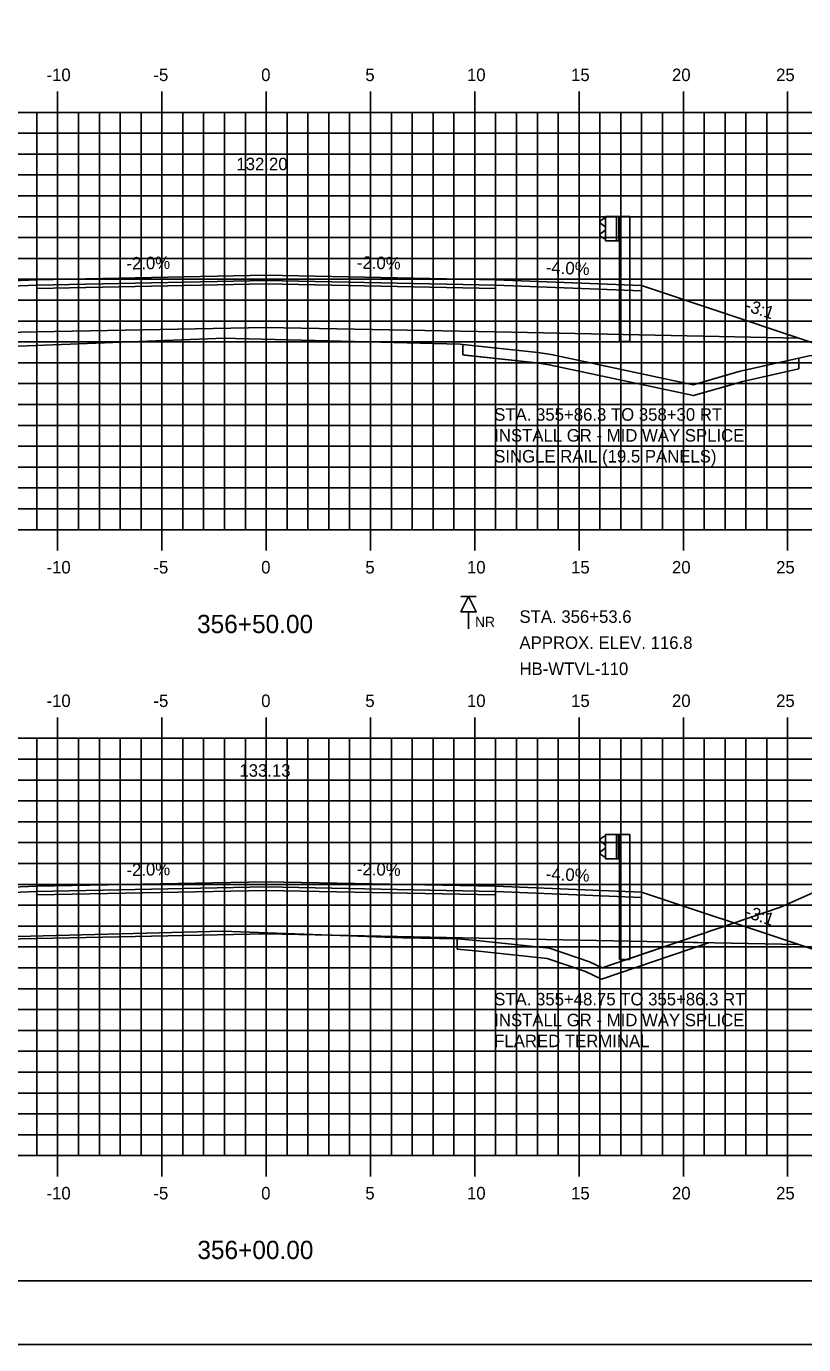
# Model space of a CAD drawing. Extents: x 1145638 to 1145808, y 608981 to 609091.
# Drawn here: x 1145709.1 to 1145746.4, y 608981.3 to 609044.5 of the extents above; entities that cross this region are included whole.
import ezdxf

# ---------------------------------------------------------------- set-up
doc = ezdxf.new("R2010")
doc.units = 0
for name, color, linetype in [('ANNOTATION', 7, 'Continuous'), ('BORDER', 7, 'Continuous'), ('D_Guardrail_Beam_Rt', 7, 'Continuous'), ('D_Guardrail_ConcBarrier', 7, 'Continuous'), ('D_Roadway_Centerline', 7, 'Continuous'), ('D_Roadway_Centerline_Text', 7, 'Continuous'), ('D_Roadway_Edge_Shoulder', 7, 'Continuous'), ('D_Roadway_Edge_TW', 7, 'Continuous'), ('D_Roadway_Pavement', 7, 'Continuous'), ('D_Roadway_SlopeLines', 7, 'Continuous'), ('D_Roadway_SubGrade', 7, 'Continuous'), ('H_V ANNOTATION', 7, 'Continuous'), ('MAJOR', 7, 'Continuous'), ('MINOR', 7, 'Continuous'), ('PLOT BOUNDARY', 7, 'Continuous'), ('ROCKS', 7, 'Continuous'), ('S_Roadway_Centerline', 7, 'Continuous'), ('SHADING', 7, 'Continuous')]:
    doc.layers.add(name, color=color, linetype=linetype)

msp = doc.modelspace()

# ---------------------------------------------------------------- linework, layer by layer
for points in [[(1145681.258, 609032.341), (1145682.508, 609032.231), (1145683.758, 609031.973), (1145685.008, 609031.568), (1145686.258, 609031.017), (1145691.284, 609028.504), (1145694.284, 609029.504), (1145701.76, 609031.996), (1145701.761, 609031.996), (1145709.645, 609032.311), (1145720.645, 609032.531), (1145731.645, 609032.311), (1145738.645, 609032.031), (1145746.177, 609029.52), (1145749.177, 609028.52), (1145749.6, 609028.71), (1145750.023, 609028.855), (1145750.446, 609028.957), (1145750.869, 609029.014)], [(1145683.903, 609003.924), (1145685.153, 609003.777), (1145686.403, 609003.494), (1145687.653, 609003.074), (1145688.903, 609002.517), (1145694.92, 608999.509), (1145697.92, 609000.509), (1145705.644, 609003.083), (1145705.645, 609003.083), (1145709.645, 609003.243), (1145720.645, 609003.463), (1145731.645, 609003.243), (1145738.645, 609002.963), (1145746.177, 609000.453), (1145749.177, 608999.453), (1145755.422, 609002.575), (1145756.672, 609003.138), (1145757.922, 609003.576), (1145759.172, 609003.888), (1145760.422, 609004.076)]]:
    msp.add_lwpolyline(points)
at = {"layer": 'BORDER'}
msp.add_lwpolyline([(1145645.645, 608984.335), (1145805.645, 608984.335), (1145805.645, 609089.335), (1145645.645, 609089.335)], close=True, dxfattribs=at)
at = {"layer": 'D_Guardrail_Beam_Rt'}
for p, q in [((1145736.828, 609035.247), (1145736.685, 609035.147)), ((1145736.685, 609035.004), (1145736.88, 609034.868)), ((1145736.918, 609035.268), (1145736.844, 609035.254)), ((1145736.914, 609034.803), (1145736.914, 609034.733)), ((1145736.88, 609034.669), (1145736.685, 609034.533)), ((1145736.685, 609034.389), (1145736.828, 609034.289)), ((1145736.844, 609034.283), (1145736.918, 609034.268)), ((1145736.916, 609005.647), (1145736.841, 609005.633)), ((1145736.826, 609005.626), (1145736.682, 609005.526)), ((1145736.682, 609005.383), (1145736.878, 609005.247)), ((1145736.878, 609005.048), (1145736.682, 609004.912)), ((1145736.911, 609005.182), (1145736.911, 609005.112)), ((1145736.682, 609004.768), (1145736.826, 609004.668)), ((1145736.841, 609004.662), (1145736.916, 609004.647))]:
    msp.add_line(p, q, dxfattribs=at)
for centre, major_axis, start_param, end_param in [((1145736.735, 609035.075), (-0.0877, 0), 5.323254, 7.243116), ((1145736.852, 609035.213), (-0.0417, 0), 4.907132, 5.323254), ((1145736.835, 609034.803), (0.0789, 0), 0, 0.959931), ((1145736.835, 609034.733), (0.0789, 0), 5.323254, 6.283185), ((1145736.735, 609034.461), (-0.0877, 0), 5.323254, 7.243116), ((1145736.852, 609034.323), (-0.0417, 0), 0.959931, 1.376053), ((1145736.85, 609005.592), (-0.0417, 0), 4.907132, 5.323254), ((1145736.732, 609005.454), (-0.0877, 0), 5.323254, 7.243116), ((1145736.832, 609005.182), (0.0789, 0), 0, 0.959931), ((1145736.832, 609005.112), (0.0789, 0), 5.323254, 6.283185), ((1145736.732, 609004.84), (-0.0877, 0), 5.323254, 7.243116), ((1145736.85, 609004.702), (-0.0417, 0), 0.959931, 1.376053)]:
    msp.add_ellipse(centre, major_axis=major_axis, ratio=0.995501, start_param=start_param, end_param=end_param, dxfattribs=at)
at = {"layer": 'D_Guardrail_ConcBarrier'}
for p, q in [((1145736.918, 609035.352), (1145737.606, 609035.352)), ((1145736.918, 609034.185), (1145736.918, 609035.352)), ((1145737.439, 609035.352), (1145737.439, 609034.185)), ((1145737.543, 609035.352), (1145737.543, 609034.185)), ((1145737.606, 609035.352), (1145738.077, 609035.352)), ((1145737.606, 609035.352), (1145737.606, 609034.185)), ((1145738.077, 609035.352), (1145738.077, 609029.352)), ((1145737.606, 609034.185), (1145736.918, 609034.185)), ((1145737.585, 609029.352), (1145737.585, 609034.185)), ((1145737.585, 609029.352), (1145738.077, 609029.352)), ((1145736.916, 609005.731), (1145737.603, 609005.731)), ((1145736.916, 609004.564), (1145736.916, 609005.731)), ((1145737.436, 609005.731), (1145737.436, 609004.564)), ((1145737.541, 609005.731), (1145737.541, 609004.564)), ((1145737.603, 609005.731), (1145738.074, 609005.731)), ((1145737.603, 609005.731), (1145737.603, 609004.564)), ((1145738.074, 609005.731), (1145738.074, 608999.731)), ((1145737.603, 609004.564), (1145736.916, 609004.564)), ((1145737.582, 608999.731), (1145737.582, 609004.564)), ((1145737.582, 608999.731), (1145738.074, 608999.731))]:
    msp.add_line(p, q, dxfattribs=at)
at = {"layer": 'D_Roadway_Edge_Shoulder'}
for points in [[(1145709.645, 609032.311), (1145701.761, 609031.996), (1145701.761, 609031.746), (1145709.645, 609032.061)], [(1145731.645, 609032.311), (1145738.645, 609032.031), (1145738.645, 609031.781), (1145731.645, 609032.061)], [(1145709.645, 609003.243), (1145705.645, 609003.083), (1145705.645, 609002.833), (1145709.645, 609002.993)], [(1145731.645, 609003.243), (1145738.645, 609002.963), (1145738.645, 609002.713), (1145731.645, 609002.993)]]:
    msp.add_lwpolyline(points, close=True, dxfattribs=at)
at = {"layer": 'D_Roadway_Edge_TW'}
for points in [[(1145709.645, 609032.061), (1145709.645, 609032.311), (1145720.645, 609032.531), (1145731.645, 609032.311), (1145731.645, 609032.061), (1145720.645, 609032.281)], [(1145709.645, 609002.993), (1145709.645, 609003.243), (1145720.645, 609003.463), (1145731.645, 609003.243), (1145731.645, 609002.993), (1145720.645, 609003.213)]]:
    msp.add_lwpolyline(points, close=True, dxfattribs=at)
at = {"layer": 'D_Roadway_Pavement'}
for points in [[(1145709.645, 609031.894), (1145709.645, 609032.061), (1145720.645, 609032.281), (1145731.645, 609032.061), (1145731.645, 609031.894), (1145720.645, 609032.114)], [(1145709.645, 609002.827), (1145709.645, 609002.993), (1145720.645, 609003.213), (1145731.645, 609002.993), (1145731.645, 609002.827), (1145720.645, 609003.047)]]:
    msp.add_lwpolyline(points, close=True, dxfattribs=at)
at = {"layer": 'D_Roadway_SlopeLines'}
for points in [[(1145746.177, 609029.52), (1145749.177, 609028.52)], [(1145746.177, 609000.453), (1145749.177, 608999.453)]]:
    msp.add_lwpolyline(points, dxfattribs=at)
at = {"layer": 'D_Roadway_SubGrade'}
for p, q in [((1145730.075, 609029.216), (1145730.075, 609028.716)), ((1145746.177, 609028.553), (1145746.177, 609028.042)), ((1145729.795, 609000.725), (1145729.795, 609000.223))]:
    msp.add_line(p, q, dxfattribs=at)
for points in [[(1145709.645, 609031.894), (1145709.645, 609032.061), (1145701.761, 609031.746), (1145701.761, 609031.996), (1145701.76, 609031.996), (1145694.284, 609029.504), (1145709.645, 609029.811)], [(1145709.645, 609029.811), (1145709.645, 609031.894), (1145720.645, 609032.114), (1145731.645, 609031.894), (1145731.645, 609029.811), (1145720.645, 609030.031)], [(1145731.645, 609031.894), (1145731.645, 609032.061), (1145738.645, 609031.781), (1145738.645, 609032.031), (1145738.645, 609032.031), (1145746.177, 609029.52), (1145731.645, 609029.811)], [(1145709.645, 609002.827), (1145709.645, 609002.993), (1145705.645, 609002.833), (1145705.645, 609003.083), (1145705.644, 609003.083), (1145697.92, 609000.509), (1145709.645, 609000.743)], [(1145709.645, 609000.743), (1145709.645, 609002.827), (1145720.645, 609003.047), (1145731.645, 609002.827), (1145731.645, 609000.743), (1145720.645, 609000.963)], [(1145731.645, 609002.827), (1145731.645, 609002.993), (1145738.645, 609002.713), (1145738.645, 609002.963), (1145738.645, 609002.963), (1145746.177, 609000.453), (1145731.645, 609000.743)]]:
    msp.add_lwpolyline(points, close=True, dxfattribs=at)
for points in [[(1145730.075, 609028.714), (1145730.157, 609028.705), (1145733.608, 609028.334), (1145734.215, 609028.241), (1145741.13, 609026.762), (1145743.498, 609027.442), (1145746.177, 609028.042)], [(1145729.795, 609000.223), (1145730.678, 609000.144), (1145734.119, 608999.779), (1145735.958, 608999.156), (1145736.723, 608998.795), (1145741.853, 609000.539)]]:
    msp.add_lwpolyline(points, dxfattribs=at)
at = {"layer": 'MAJOR'}
for p, q in [((1145710.645, 609041.337), (1145710.645, 609040.335)), ((1145715.645, 609041.337), (1145715.645, 609040.335)), ((1145720.645, 609041.337), (1145720.645, 609040.335)), ((1145725.645, 609041.337), (1145725.645, 609040.335)), ((1145730.645, 609041.337), (1145730.645, 609040.335)), ((1145735.645, 609041.337), (1145735.645, 609040.335)), ((1145740.645, 609041.337), (1145740.645, 609040.335)), ((1145745.645, 609041.337), (1145745.645, 609040.335)), ((1145650.645, 609040.335), (1145790.645, 609040.335)), ((1145650.645, 609040.335), (1145790.645, 609040.335)), ((1145710.645, 609020.335), (1145710.645, 609040.335)), ((1145715.645, 609020.335), (1145715.645, 609040.335)), ((1145720.645, 609020.335), (1145720.645, 609040.335)), ((1145725.645, 609020.335), (1145725.645, 609040.335)), ((1145730.645, 609020.335), (1145730.645, 609040.335)), ((1145735.645, 609020.335), (1145735.645, 609040.335)), ((1145740.645, 609020.335), (1145740.645, 609040.335)), ((1145745.645, 609020.335), (1145745.645, 609040.335)), ((1145650.645, 609035.335), (1145790.645, 609035.335)), ((1145650.645, 609030.335), (1145790.645, 609030.335)), ((1145650.645, 609025.335), (1145790.645, 609025.335)), ((1145650.645, 609020.335), (1145790.645, 609020.335)), ((1145650.645, 609020.335), (1145790.645, 609020.335)), ((1145710.645, 609019.333), (1145710.645, 609020.335)), ((1145715.645, 609019.333), (1145715.645, 609020.335)), ((1145720.645, 609019.333), (1145720.645, 609020.335)), ((1145725.645, 609019.333), (1145725.645, 609020.335)), ((1145730.645, 609019.333), (1145730.645, 609020.335)), ((1145735.645, 609019.333), (1145735.645, 609020.335)), ((1145740.645, 609019.333), (1145740.645, 609020.335)), ((1145745.645, 609019.333), (1145745.645, 609020.335)), ((1145710.645, 609011.337), (1145710.645, 609010.335)), ((1145715.645, 609011.337), (1145715.645, 609010.335)), ((1145720.645, 609011.337), (1145720.645, 609010.335)), ((1145725.645, 609011.337), (1145725.645, 609010.335)), ((1145730.645, 609011.337), (1145730.645, 609010.335)), ((1145735.645, 609011.337), (1145735.645, 609010.335)), ((1145740.645, 609011.337), (1145740.645, 609010.335)), ((1145745.645, 609011.337), (1145745.645, 609010.335)), ((1145650.645, 609010.335), (1145790.645, 609010.335)), ((1145650.645, 609010.335), (1145790.645, 609010.335)), ((1145710.645, 608990.335), (1145710.645, 609010.335)), ((1145715.645, 608990.335), (1145715.645, 609010.335)), ((1145720.645, 608990.335), (1145720.645, 609010.335)), ((1145725.645, 608990.335), (1145725.645, 609010.335)), ((1145730.645, 608990.335), (1145730.645, 609010.335)), ((1145735.645, 608990.335), (1145735.645, 609010.335)), ((1145740.645, 608990.335), (1145740.645, 609010.335)), ((1145745.645, 608990.335), (1145745.645, 609010.335)), ((1145650.645, 609005.335), (1145790.645, 609005.335)), ((1145650.645, 609000.335), (1145790.645, 609000.335)), ((1145650.645, 608995.335), (1145790.645, 608995.335)), ((1145650.645, 608990.335), (1145790.645, 608990.335)), ((1145650.645, 608990.335), (1145790.645, 608990.335)), ((1145710.645, 608989.333), (1145710.645, 608990.335)), ((1145715.645, 608989.333), (1145715.645, 608990.335)), ((1145720.645, 608989.333), (1145720.645, 608990.335)), ((1145725.645, 608989.333), (1145725.645, 608990.335)), ((1145730.645, 608989.333), (1145730.645, 608990.335)), ((1145735.645, 608989.333), (1145735.645, 608990.335)), ((1145740.645, 608989.333), (1145740.645, 608990.335)), ((1145745.645, 608989.333), (1145745.645, 608990.335))]:
    msp.add_line(p, q, dxfattribs=at)
at = {"layer": 'MINOR'}
for p, q in [((1145709.645, 609020.335), (1145709.645, 609040.335)), ((1145711.645, 609020.335), (1145711.645, 609040.335)), ((1145712.645, 609020.335), (1145712.645, 609040.335)), ((1145713.645, 609020.335), (1145713.645, 609040.335)), ((1145714.645, 609020.335), (1145714.645, 609040.335)), ((1145716.645, 609020.335), (1145716.645, 609040.335)), ((1145717.645, 609020.335), (1145717.645, 609040.335)), ((1145718.645, 609020.335), (1145718.645, 609040.335)), ((1145719.645, 609020.335), (1145719.645, 609040.335)), ((1145721.645, 609020.335), (1145721.645, 609040.335)), ((1145722.645, 609020.335), (1145722.645, 609040.335)), ((1145723.645, 609020.335), (1145723.645, 609040.335)), ((1145724.645, 609020.335), (1145724.645, 609040.335)), ((1145726.645, 609020.335), (1145726.645, 609040.335)), ((1145727.645, 609020.335), (1145727.645, 609040.335)), ((1145728.645, 609020.335), (1145728.645, 609040.335)), ((1145729.645, 609020.335), (1145729.645, 609040.335)), ((1145731.645, 609020.335), (1145731.645, 609040.335)), ((1145732.645, 609020.335), (1145732.645, 609040.335)), ((1145733.645, 609020.335), (1145733.645, 609040.335)), ((1145734.645, 609020.335), (1145734.645, 609040.335)), ((1145736.645, 609020.335), (1145736.645, 609040.335)), ((1145737.645, 609020.335), (1145737.645, 609040.335)), ((1145738.645, 609020.335), (1145738.645, 609040.335)), ((1145739.645, 609020.335), (1145739.645, 609040.335)), ((1145741.645, 609020.335), (1145741.645, 609040.335)), ((1145742.645, 609020.335), (1145742.645, 609040.335)), ((1145743.645, 609020.335), (1145743.645, 609040.335)), ((1145744.645, 609020.335), (1145744.645, 609040.335)), ((1145650.645, 609039.335), (1145790.645, 609039.335)), ((1145650.645, 609038.335), (1145790.645, 609038.335)), ((1145650.645, 609037.335), (1145790.645, 609037.335)), ((1145650.645, 609036.335), (1145790.645, 609036.335)), ((1145650.645, 609034.335), (1145790.645, 609034.335)), ((1145650.645, 609033.335), (1145790.645, 609033.335)), ((1145650.645, 609032.335), (1145790.645, 609032.335)), ((1145650.645, 609031.335), (1145790.645, 609031.335)), ((1145650.645, 609029.335), (1145790.645, 609029.335)), ((1145650.645, 609028.335), (1145790.645, 609028.335)), ((1145650.645, 609027.335), (1145790.645, 609027.335)), ((1145650.645, 609026.335), (1145790.645, 609026.335)), ((1145650.645, 609024.335), (1145790.645, 609024.335)), ((1145650.645, 609023.335), (1145790.645, 609023.335)), ((1145650.645, 609022.335), (1145790.645, 609022.335)), ((1145650.645, 609021.335), (1145790.645, 609021.335)), ((1145709.645, 608990.335), (1145709.645, 609010.335)), ((1145711.645, 608990.335), (1145711.645, 609010.335)), ((1145712.645, 608990.335), (1145712.645, 609010.335)), ((1145713.645, 608990.335), (1145713.645, 609010.335)), ((1145714.645, 608990.335), (1145714.645, 609010.335)), ((1145716.645, 608990.335), (1145716.645, 609010.335)), ((1145717.645, 608990.335), (1145717.645, 609010.335)), ((1145718.645, 608990.335), (1145718.645, 609010.335)), ((1145719.645, 608990.335), (1145719.645, 609010.335)), ((1145721.645, 608990.335), (1145721.645, 609010.335)), ((1145722.645, 608990.335), (1145722.645, 609010.335)), ((1145723.645, 608990.335), (1145723.645, 609010.335)), ((1145724.645, 608990.335), (1145724.645, 609010.335)), ((1145726.645, 608990.335), (1145726.645, 609010.335)), ((1145727.645, 608990.335), (1145727.645, 609010.335)), ((1145728.645, 608990.335), (1145728.645, 609010.335)), ((1145729.645, 608990.335), (1145729.645, 609010.335)), ((1145731.645, 608990.335), (1145731.645, 609010.335)), ((1145732.645, 608990.335), (1145732.645, 609010.335)), ((1145733.645, 608990.335), (1145733.645, 609010.335)), ((1145734.645, 608990.335), (1145734.645, 609010.335)), ((1145736.645, 608990.335), (1145736.645, 609010.335)), ((1145737.645, 608990.335), (1145737.645, 609010.335)), ((1145738.645, 608990.335), (1145738.645, 609010.335)), ((1145739.645, 608990.335), (1145739.645, 609010.335)), ((1145741.645, 608990.335), (1145741.645, 609010.335)), ((1145742.645, 608990.335), (1145742.645, 609010.335)), ((1145743.645, 608990.335), (1145743.645, 609010.335)), ((1145744.645, 608990.335), (1145744.645, 609010.335)), ((1145650.645, 609009.335), (1145790.645, 609009.335)), ((1145650.645, 609008.335), (1145790.645, 609008.335)), ((1145650.645, 609007.335), (1145790.645, 609007.335)), ((1145650.645, 609006.335), (1145790.645, 609006.335)), ((1145650.645, 609004.335), (1145790.645, 609004.335)), ((1145650.645, 609003.335), (1145790.645, 609003.335)), ((1145650.645, 609002.335), (1145790.645, 609002.335)), ((1145650.645, 609001.335), (1145790.645, 609001.335)), ((1145650.645, 608999.335), (1145790.645, 608999.335)), ((1145650.645, 608998.335), (1145790.645, 608998.335)), ((1145650.645, 608997.335), (1145790.645, 608997.335)), ((1145650.645, 608996.335), (1145790.645, 608996.335)), ((1145650.645, 608994.335), (1145790.645, 608994.335)), ((1145650.645, 608993.335), (1145790.645, 608993.335)), ((1145650.645, 608992.335), (1145790.645, 608992.335)), ((1145650.645, 608991.335), (1145790.645, 608991.335))]:
    msp.add_line(p, q, dxfattribs=at)
at = {"layer": 'PLOT BOUNDARY'}
msp.add_lwpolyline([(1145637.552, 608981.276), (1145807.552, 608981.276), (1145807.552, 609091.276), (1145637.552, 609091.276)], close=True, dxfattribs=at)
at = {"layer": 'ROCKS'}
for p, q in [((1145730.714, 609017.135), (1145729.976, 609017.135)), ((1145730.345, 609016.397), (1145730.345, 609015.582))]:
    msp.add_line(p, q, dxfattribs=at)
msp.add_lwpolyline([(1145730.345, 609017.135), (1145730.714, 609016.397), (1145729.976, 609016.397)], close=True, dxfattribs=at)
at = {"layer": 'S_Roadway_Centerline'}
for points in [[(1145669.136, 609032.753), (1145680.62, 609032.361), (1145689.164, 609032.105), (1145700.503, 609028.355), (1145700.592, 609028.328), (1145700.97, 609028.382), (1145704.281, 609028.863), (1145704.322, 609028.867), (1145707.646, 609029.095), (1145707.961, 609029.103), (1145718.638, 609029.518), (1145719.177, 609029.498), (1145729.939, 609029.23), (1145730.211, 609029.201), (1145733.672, 609028.828), (1145734.305, 609028.732), (1145741.113, 609027.276), (1145743.374, 609027.926), (1145746.672, 609028.664), (1145751.599, 609029.075), (1145765.021, 609029.966)], [(1145665.284, 609004.253), (1145674.048, 609004.329), (1145676.611, 609004.338), (1145686.027, 609003.803), (1145691.493, 609003.283), (1145697.515, 609000.943), (1145701.06, 608999.985), (1145703.047, 609000.3), (1145704.751, 609000.59), (1145706.442, 609000.759), (1145707.087, 609000.832), (1145707.467, 609000.81), (1145715.52, 609001.007), (1145718.557, 609001.09), (1145727.194, 609000.779), (1145729.795, 609000.725), (1145730.727, 609000.642), (1145734.227, 609000.27), (1145736.145, 608999.62), (1145736.754, 608999.333), (1145745.298, 609002.239), (1145746.848, 609002.934), (1145749.998, 609003.03), (1145766.074, 609004.643)]]:
    msp.add_lwpolyline(points, dxfattribs=at)
at = {"layer": 'SHADING'}
for p, q in [((1145730.075, 609029.216), (1145730.075, 609028.716)), ((1145746.177, 609028.553), (1145743.374, 609027.926)), ((1145746.177, 609028.042), (1145746.177, 609028.553)), ((1145729.795, 609000.725), (1145729.795, 609000.223)), ((1145740.386, 609000.569), (1145738.074, 608999.782)), ((1145741.853, 609000.539), (1145740.386, 609000.569)), ((1145738.074, 608999.731), (1145737.922, 608999.731)), ((1145738.074, 608999.782), (1145738.074, 608999.731))]:
    msp.add_line(p, q, dxfattribs=at)
for points in [[(1145743.374, 609027.926), (1145741.113, 609027.276), (1145734.305, 609028.732), (1145733.672, 609028.828), (1145730.211, 609029.201), (1145730.075, 609029.216)], [(1145730.075, 609028.716), (1145733.608, 609028.334), (1145734.215, 609028.241), (1145741.13, 609026.762), (1145743.498, 609027.442), (1145746.177, 609028.042)], [(1145737.922, 608999.731), (1145736.754, 608999.333), (1145736.145, 608999.62), (1145734.227, 609000.27), (1145730.727, 609000.642), (1145729.795, 609000.725)], [(1145729.795, 609000.223), (1145730.678, 609000.144), (1145734.119, 608999.779), (1145735.958, 608999.156), (1145736.723, 608998.795), (1145741.853, 609000.539)]]:
    msp.add_lwpolyline(points, dxfattribs=at)

# ---------------------------------------------------------------- texts
at = {"layer": 'ANNOTATION'}
for s, rotation, p in [('-2.0%', 1.14576, (1145713.948, 609032.797)), ('-2.0%', 358.85424, (1145724.988, 609032.844)), ('-4.0%', 357.70939, (1145734.041, 609032.616)), ('-3:1', 341.56522, (1145743.561, 609030.847)), ('-2.0%', 1.14576, (1145713.948, 609003.73)), ('-2.0%', 358.85424, (1145724.988, 609003.777)), ('-4.0%', 357.70939, (1145734.041, 609003.548)), ('-3:1', 341.56522, (1145743.561, 609001.779))]:
    msp.add_text(s, height=0.6, rotation=rotation, dxfattribs=at).set_placement(p)
for s, p in [('STA. 355+86.3 TO 358+30 RT', (1145731.575, 609025.558)), ('INSTALL GR - MID WAY SPLICE', (1145731.575, 609024.556)), ('SINGLE RAIL (19.5 PANELS)', (1145731.575, 609023.554)), ('STA. 355+48.75 TO 355+86.3 RT', (1145731.575, 608997.536)), ('INSTALL GR - MID WAY SPLICE', (1145731.575, 608996.534)), ('FLARED TERMINAL', (1145731.575, 608995.532))]:
    msp.add_text(s, height=0.6, dxfattribs=at).set_placement(p)
at = {"layer": 'D_Roadway_Centerline'}
for s, p in [('C', (1145720.64, 609032.531)), ('L', (1145720.645, 609032.524)), ('C', (1145720.64, 609003.463)), ('L', (1145720.645, 609003.456))]:
    msp.add_text(s, height=0.0146, dxfattribs=at).set_placement(p)
at = {"layer": 'D_Roadway_Centerline_Text'}
for s, p in [('132.20', (1145719.216, 609037.563)), ('133.13', (1145719.358, 609008.495))]:
    msp.add_text(s, height=0.6, dxfattribs=at).set_placement(p)
at = {"layer": 'H_V ANNOTATION'}
for s, height, p in [('-10', 0.6, (1145710.11, 609041.835)), ('-5', 0.6, (1145715.236, 609041.835)), ('0', 0.6, (1145720.404, 609041.835)), ('5', 0.6, (1145725.396, 609041.835)), ('10', 0.6, (1145730.27, 609041.835)), ('15', 0.6, (1145735.262, 609041.835)), ('20', 0.6, (1145740.099, 609041.835)), ('25', 0.6, (1145745.091, 609041.835)), ('-10', 0.6, (1145710.11, 609018.235)), ('-5', 0.6, (1145715.236, 609018.235)), ('0', 0.6, (1145720.404, 609018.235)), ('5', 0.6, (1145725.396, 609018.235)), ('10', 0.6, (1145730.27, 609018.235)), ('15', 0.6, (1145735.262, 609018.235)), ('20', 0.6, (1145740.099, 609018.235)), ('25', 0.6, (1145745.091, 609018.235)), ('356+50.00', 0.875, (1145717.329, 609015.378)), ('-10', 0.6, (1145710.11, 609011.835)), ('-5', 0.6, (1145715.236, 609011.835)), ('0', 0.6, (1145720.404, 609011.835)), ('5', 0.6, (1145725.396, 609011.835)), ('10', 0.6, (1145730.27, 609011.835)), ('15', 0.6, (1145735.262, 609011.835)), ('20', 0.6, (1145740.099, 609011.835)), ('25', 0.6, (1145745.091, 609011.835)), ('-10', 0.6, (1145710.11, 608988.235)), ('-5', 0.6, (1145715.236, 608988.235)), ('0', 0.6, (1145720.404, 608988.235)), ('5', 0.6, (1145725.396, 608988.235)), ('10', 0.6, (1145730.27, 608988.235)), ('15', 0.6, (1145735.262, 608988.235)), ('20', 0.6, (1145740.099, 608988.235)), ('25', 0.6, (1145745.091, 608988.235)), ('356+00.00', 0.875, (1145717.344, 608985.378))]:
    msp.add_text(s, height=height, dxfattribs=at).set_placement(p)
at = {"layer": 'ROCKS'}
for s, p in [('STA. 356+53.6', (1145732.787, 609015.87)), ('APPROX. ELEV. 116.8', (1145732.787, 609014.62)), ('HB-WTVL-110', (1145732.787, 609013.37))]:
    msp.add_text(s, height=0.6, rotation=360, dxfattribs=at).set_placement(p)
msp.add_text('NR', height=0.4921, dxfattribs=at).set_placement((1145730.66, 609015.67))
at = {"layer": 'S_Roadway_Centerline'}
for s, p in [('L', (1145718.629, 609029.51)), ('C', (1145718.632, 609029.518)), ('L', (1145718.549, 609001.083)), ('C', (1145718.552, 609001.09))]:
    msp.add_text(s, height=0.0146, dxfattribs=at).set_placement(p)

doc.saveas('drawing.dxf')
